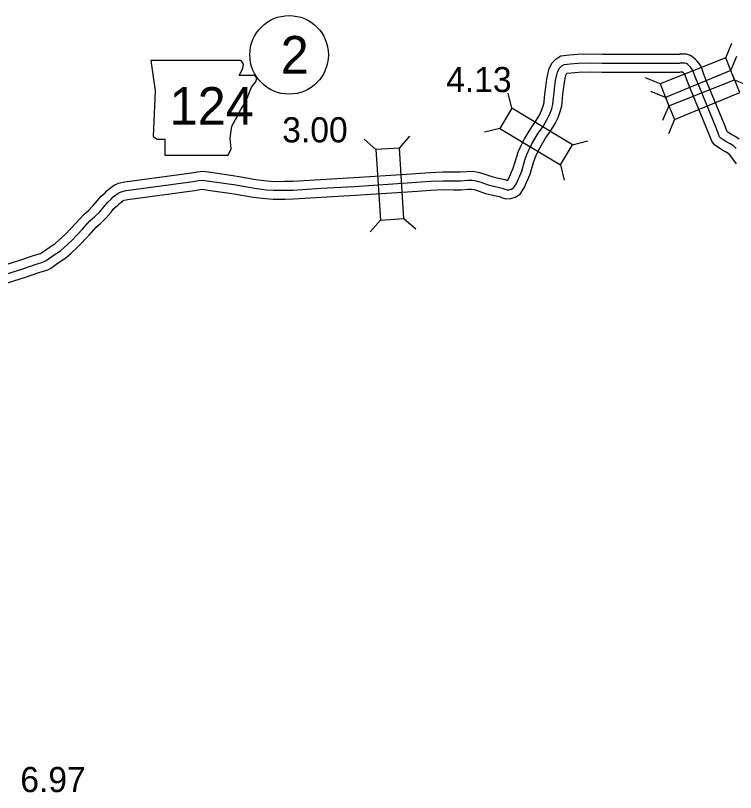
# Model space of a CAD drawing. Extents: x -83719 to 153526, y -11835 to 11446.
# Drawn here: x -1067.2 to -664, y 1687 to 2121.8 of the extents above; entities that cross this region are included whole.
import ezdxf

# ---------------------------------------------------------------- set-up
doc = ezdxf.new("R2010")
doc.units = 0
for name, color, linetype in [('Level 11', 7, 'Continuous'), ('Level 20', 7, 'Continuous'), ('Level 21', 7, 'Continuous'), ('Level 27', 7, 'Continuous'), ('Level 58', 7, 'Continuous'), ('Level 59', 7, 'Continuous')]:
    doc.layers.add(name, color=color, linetype=linetype)

msp = doc.modelspace()

# ---------------------------------------------------------------- linework, layer by layer
at = {"layer": 'Level 11'}
for points in [[(-1087.92, 1977.62), (-1064.68, 1984.87), (-1057.12, 1987.51), (-1054.49, 1988.22), (-1053.17, 1988.71), (-1052.59, 1989.01), (-1048.39, 1991.96), (-1045.06, 1994.17), (-1043.11, 1995.86), (-1039.2, 1999.46), (-1033.35, 2005.6), (-1028.99, 2010.45), (-1026.32, 2012.76), (-1023.69, 2015.42), (-1021.27, 2018.26), (-1019.24, 2020.68), (-1017.03, 2022.68), (-1015.82, 2023.95), (-1014.06, 2025.4), (-1011.85, 2026.95), (-1009.58, 2027.99), (-1006.04, 2028.78), (-968.55, 2033.81), (-965.32, 2034.43), (-962.25, 2034.73), (-957.74, 2034.07), (-943.04, 2031.95), (-932.55, 2030.06), (-926.22, 2029.34), (-922.44, 2028.99), (-916.47, 2029.1), (-911.79, 2029.14), (-896.32, 2030.12), (-877.54, 2031.21), (-848.21, 2033.11), (-842.88, 2033.46), (-835.12, 2034.04), (-827.88, 2034.38), (-821.69, 2034.28), (-818.04, 2034.27), (-814.32, 2034.58), (-811.16, 2034.69), (-808.12, 2034.22), (-804.93, 2033.27), (-801.05, 2031.84), (-798.39, 2031.23), (-795.75, 2030.68), (-793.13, 2030.04), (-791.56, 2029.44), (-791.05, 2030.21), (-788.39, 2036.33), (-786.66, 2042.42), (-785.52, 2045.91), (-784.41, 2048.34), (-782.11, 2052.89), (-778.65, 2058.65), (-775.91, 2062.51), (-773.77, 2066.12), (-772.53, 2068.65), (-771.65, 2071.18), (-771.1, 2073.09), (-770.82, 2076.06), (-770.51, 2079.03), (-770.2, 2081.64), (-769.67, 2086.26), (-768.91, 2089.73), (-768.36, 2091.96), (-766.73, 2095.15), (-764.4, 2097.53), (-761.68, 2099.27), (-756.98, 2099.78), (-752.4, 2100.2), (-745.11, 2100.3), (-738.48, 2100.11), (-695.04, 2100.14)], [(-661.94, 2052.69), (-664.47, 2054.26), (-666.23, 2055.2), (-667.74, 2056.14), (-668.54, 2056.73), (-669.76, 2059.91), (-679.75, 2084.08), (-681.84, 2089.32), (-682.7, 2091.77), (-683.26, 2093.3), (-684.3, 2095.06), (-685.43, 2096.3), (-686.31, 2097.14), (-687.57, 2098.36), (-689.09, 2099.38), (-691.37, 2100.25), (-693.56, 2100.2), (-695.24, 2100.14)], [(-1084.91, 1968.08), (-1061.54, 1975.37), (-1054.16, 1977.95), (-1051.43, 1978.69), (-1049.12, 1979.55), (-1047.4, 1980.43), (-1042.75, 1983.7), (-1038.99, 1986.19), (-1036.44, 1988.4), (-1032.19, 1992.33), (-1026.01, 1998.81), (-1021.98, 2003.3), (-1019.49, 2005.45), (-1016.33, 2008.65), (-1013.63, 2011.81), (-1012.02, 2013.73), (-1010.05, 2015.51), (-1008.99, 2016.62), (-1008, 2017.44), (-1006.86, 2018.23), (-1006.37, 2018.46), (-1004.28, 2018.93), (-966.94, 2023.94), (-963.88, 2024.53), (-962.5, 2024.66), (-959.19, 2024.17), (-944.64, 2022.08), (-934, 2020.17), (-927.25, 2019.39), (-922.81, 2018.98), (-916.34, 2019.1), (-911.43, 2019.14), (-895.72, 2020.13), (-876.93, 2021.23), (-847.55, 2023.13), (-842.18, 2023.49), (-834.51, 2024.06), (-827.72, 2024.37), (-821.78, 2024.28), (-817.64, 2024.26), (-813.72, 2024.59), (-811.76, 2024.66), (-810.32, 2024.44), (-808.08, 2023.77), (-803.91, 2022.24), (-800.54, 2021.46), (-797.96, 2020.93), (-796.1, 2020.47), (-794.92, 2020.02), (-792.58, 2019.2), (-789.82, 2019.35), (-787.36, 2020.17), (-784.62, 2021.83), (-782.24, 2025.4), (-778.95, 2032.96), (-777.1, 2039.5), (-776.19, 2042.27), (-775.39, 2044.01), (-773.35, 2048.05), (-770.27, 2053.18), (-767.52, 2057.06), (-764.97, 2061.36), (-763.29, 2064.77), (-762.11, 2068.16), (-761.23, 2071.23), (-760.87, 2075.08), (-760.57, 2077.92), (-760.27, 2080.47), (-759.79, 2084.61), (-759.17, 2087.46), (-758.93, 2088.44), (-758.51, 2089.24), (-758.18, 2089.59), (-755.99, 2089.83), (-751.87, 2090.21), (-745.18, 2090.29), (-738.62, 2090.11), (-695.03, 2090.14)], [(-663.39, 2038.89), (-665.46, 2041.66), (-667.25, 2044.02), (-667.96, 2044.65), (-669.47, 2045.6), (-671.22, 2046.53), (-673.36, 2047.86), (-675.63, 2049.54), (-677.23, 2051.46), (-679.05, 2056.21), (-689.01, 2080.32), (-691.2, 2085.81), (-692.11, 2088.4), (-692.33, 2088.99), (-692.38, 2089.08), (-692.62, 2089.34), (-693.24, 2089.94), (-693.51, 2090.2), (-694.84, 2090.14)]]:
    msp.add_lwpolyline(points, dxfattribs=at)
at = {"layer": 'Level 20'}
for p, q in [((-669.44, 2098.18), (-665.96, 2106.26)), ((-666.61, 2091.03), (-663.23, 2099.16)), ((-706.22, 2083.51), (-714.3, 2086.98)), ((-664.55, 2085.92), (-656.46, 2082.44)), ((-789.14, 2069.92), (-791.27, 2078.46)), ((-703.2, 2075.9), (-711.33, 2079.27)), ((-701.33, 2071.25), (-704.81, 2063.16)), ((-698.16, 2063.7), (-701.53, 2055.57)), ((-795.94, 2058.61), (-804.48, 2056.48)), ((-865.37, 2046.83), (-871.98, 2052.64)), ((-852.2, 2047.68), (-846.39, 2054.29)), ((-755.2, 2049.52), (-746.66, 2051.65)), ((-762, 2038.21), (-759.87, 2029.67)), ((-862.81, 2007.31), (-868.62, 2000.7)), ((-849.64, 2008.16), (-843.03, 2002.36))]:
    msp.add_line(p, q, dxfattribs=at)
for points in [[(-669.44, 2098.18), (-706.22, 2083.51), (-701.33, 2071.25), (-664.55, 2085.92)], [(-666.61, 2091.03), (-703.2, 2075.9), (-698.16, 2063.7), (-661.56, 2078.83)], [(-795.94, 2058.61), (-762, 2038.21), (-755.2, 2049.52), (-789.14, 2069.92)], [(-865.37, 2046.83), (-862.81, 2007.31), (-849.64, 2008.16), (-852.2, 2047.68)]]:
    msp.add_lwpolyline(points, close=True, dxfattribs=at)
at = {"layer": 'Level 21'}
msp.add_lwpolyline([(-991.46, 2096.63), (-988.92, 2079.71), (-990.05, 2054.05), (-987.79, 2052.64), (-983.56, 2052.64), (-983.56, 2043.62), (-948.04, 2043.62), (-946.34, 2047.28), (-946.91, 2053.2), (-946.06, 2059.97), (-942.96, 2065.33), (-940.99, 2069.27), (-938.17, 2073.5), (-936.48, 2078.02), (-935.07, 2081.68), (-932.53, 2084.78), (-931.96, 2086.76), (-933.09, 2088.17), (-941.83, 2088.17), (-939.86, 2092.11), (-939.58, 2094.65), (-940.75, 2096.6)], close=True, dxfattribs=at)
at = {"layer": 'Level 27'}
msp.add_circle((-913.93, 2099.81), 22, dxfattribs=at)
at = {"layer": 'Level 59'}
for points in [[(-1086.42, 1972.85), (-1063.11, 1980.12), (-1055.64, 1982.73), (-1052.96, 1983.45), (-1051.15, 1984.13), (-1049.99, 1984.72), (-1045.57, 1987.83), (-1042.03, 1990.18), (-1039.77, 1992.13), (-1035.69, 1995.89), (-1029.68, 2002.21), (-1025.49, 2006.87), (-1022.91, 2009.1), (-1020.01, 2012.04), (-1017.45, 2015.03), (-1015.63, 2017.21), (-1013.54, 2019.09), (-1012.4, 2020.29), (-1011.03, 2021.42), (-1009.36, 2022.59), (-1007.97, 2023.22), (-1005.16, 2023.85), (-967.75, 2028.87), (-964.6, 2029.48), (-962.37, 2029.7), (-958.47, 2029.12), (-943.84, 2027.01), (-933.27, 2025.12), (-926.73, 2024.36), (-922.63, 2023.99), (-916.41, 2024.1), (-911.61, 2024.14), (-896.02, 2025.13), (-877.23, 2026.22), (-847.88, 2028.12), (-842.53, 2028.47), (-834.82, 2029.05), (-827.8, 2029.37), (-821.74, 2029.28), (-817.84, 2029.27), (-814.02, 2029.59), (-811.46, 2029.68), (-809.22, 2029.33), (-806.51, 2028.52), (-802.48, 2027.04), (-799.47, 2026.34), (-796.86, 2025.8), (-794.61, 2025.25), (-793.2, 2024.72), (-791.86, 2024.25), (-790.76, 2024.31), (-789.48, 2024.73), (-788.16, 2025.53), (-786.65, 2027.8), (-783.67, 2034.65), (-781.88, 2040.96), (-780.85, 2044.09), (-779.9, 2046.18), (-777.73, 2050.47), (-774.46, 2055.91), (-771.72, 2059.78), (-769.37, 2063.74), (-767.91, 2066.71), (-766.88, 2069.67), (-766.17, 2072.16), (-765.84, 2075.57), (-765.54, 2078.48), (-765.23, 2081.06), (-764.73, 2085.44), (-764.04, 2088.59), (-763.64, 2090.2), (-762.62, 2092.2), (-761.22, 2093.63), (-759.97, 2094.43), (-756.49, 2094.8), (-752.13, 2095.2), (-745.14, 2095.3), (-738.55, 2095.11), (-695.04, 2095.14)], [(-663.56, 2047.43), (-664.95, 2048.67), (-666.97, 2049.93), (-668.73, 2050.86), (-670.55, 2052), (-672.17, 2053.2), (-672.86, 2054.02), (-674.4, 2058.06), (-684.38, 2082.2), (-686.52, 2087.56), (-687.4, 2090.08), (-687.79, 2091.14), (-688.34, 2092.07), (-689.03, 2092.82), (-689.77, 2093.54), (-690.72, 2094.46), (-691.4, 2094.91), (-692.24, 2095.23), (-693.41, 2095.21), (-695.04, 2095.14)]]:
    msp.add_lwpolyline(points, dxfattribs=at)

# ---------------------------------------------------------------- texts
at = {"layer": 'Level 21'}
msp.add_text('124', height=21.12, dxfattribs=at).set_placement((-980.87, 2060.65))
at = {"layer": 'Level 27'}
msp.add_text('2', height=21.12, dxfattribs=at).set_placement((-918.66, 2089.25))
at = {"layer": 'Level 58'}
for s, p in [('4.13', (-825.97, 2078.99)), ('3.00', (-917.79, 2050.83)), ('6.97', (-1064.49, 1687.21))]:
    msp.add_text(s, height=14.08, dxfattribs=at).set_placement(p)

doc.saveas('drawing.dxf')
